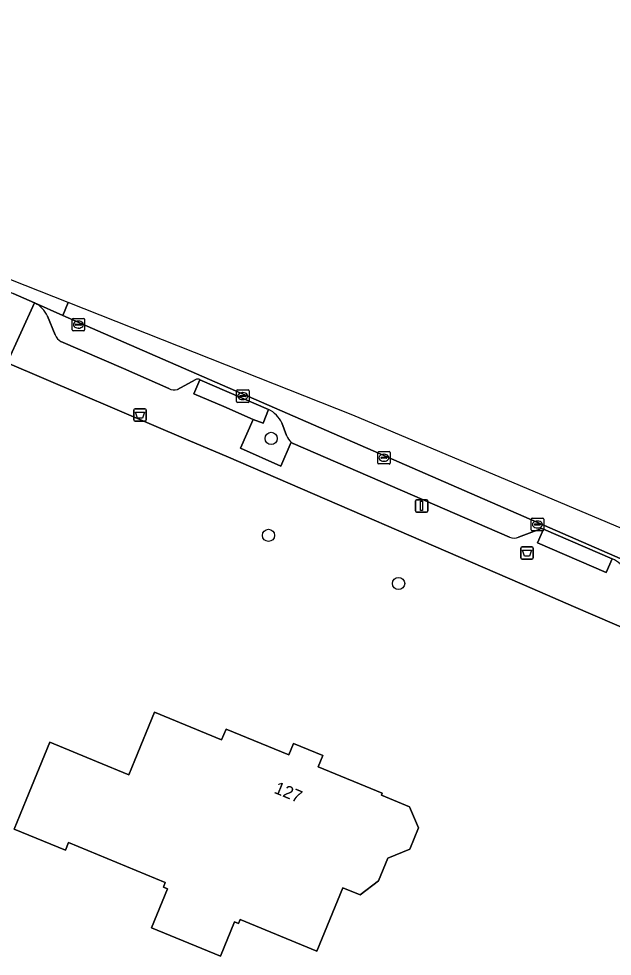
# Model space of a CAD drawing. Extents: x 159371 to 159986, y 382987 to 383597.
# Drawn here: x 159771.8 to 159819.4, y 383510.4 to 383585.6 of the extents above; entities that cross this region are included whole.
import ezdxf

# ---------------------------------------------------------------- set-up
doc = ezdxf.new("R2010")
doc.units = 0
for name, color, linetype in [('IMGEO_Afvalbak', 7, 'Continuous'), ('IMGEO_Boom', 7, 'Continuous'), ('IMGEO_Erf', 7, 'Continuous'), ('IMGEO_Groenvoorziening', 7, 'Continuous'), ('IMGEO_Kolk', 7, 'Continuous'), ('IMGEO_Lichtmast', 7, 'Continuous'), ('IMGEO_Pand', 7, 'Continuous'), ('IMGEO_Pand_nummerreeks', 7, 'Continuous'), ('IMGEO_Parkeervlak_open', 7, 'Continuous'), ('IMGEO_Rijbaan_lokaal_open', 7, 'Continuous'), ('IMGEO_Voetpad_open', 7, 'Continuous')]:
    doc.layers.add(name, color=color, linetype=linetype)

msp = doc.modelspace()

# ---------------------------------------------------------------- linework, layer by layer
at = {"layer": 'IMGEO_Afvalbak'}
for p, q in [((159780.996, 383553.438), (159780.996, 383554.238)), ((159780.996, 383554.238), (159780.996, 383553.438)), ((159781.096, 383554.338), (159781.886, 383554.338)), ((159781.886, 383554.338), (159781.096, 383554.338)), ((159781.986, 383554.238), (159781.986, 383553.438)), ((159781.986, 383553.438), (159781.986, 383554.238)), ((159781.886, 383553.338), (159781.096, 383553.338)), ((159781.096, 383553.338), (159781.886, 383553.338)), ((159812.046, 383542.362), (159812.046, 383543.162)), ((159812.046, 383543.162), (159812.046, 383542.362)), ((159812.146, 383543.262), (159812.936, 383543.262)), ((159812.936, 383543.262), (159812.146, 383543.262)), ((159813.036, 383543.162), (159813.036, 383542.362)), ((159813.036, 383542.362), (159813.036, 383543.162)), ((159812.936, 383542.262), (159812.146, 383542.262)), ((159812.146, 383542.262), (159812.936, 383542.262))]:
    msp.add_line(p, q, dxfattribs=at)
for points in [[(159781.139, 383554.052), (159781.843, 383554.052), (159781.694, 383553.582), (159781.288, 383553.582), (159781.139, 383554.052)], [(159812.189, 383542.976), (159812.893, 383542.976), (159812.744, 383542.506), (159812.338, 383542.506), (159812.189, 383542.976)]]:
    msp.add_lwpolyline(points, dxfattribs=at)
for centre, start, end in [((159781.096, 383554.238), 90, 180), ((159781.096, 383554.238), 90, 180), ((159781.886, 383554.238), 0, 90), ((159781.886, 383554.238), 360, 90), ((159781.096, 383553.438), 180, 270), ((159781.096, 383553.438), 180, 270), ((159781.886, 383553.438), 270, 0), ((159781.886, 383553.438), 270, 0), ((159812.146, 383543.162), 90, 180), ((159812.146, 383543.162), 90, 180), ((159812.936, 383543.162), 0, 90), ((159812.936, 383543.162), 360, 90), ((159812.146, 383542.362), 180, 270), ((159812.146, 383542.362), 180, 270), ((159812.936, 383542.362), 270, 0), ((159812.936, 383542.362), 270, 0)]:
    msp.add_arc(centre, 0.1, start, end, dxfattribs=at)
at = {"layer": 'IMGEO_Boom'}
for centre in [(159792.012, 383551.954), (159791.801, 383544.177), (159802.241, 383540.317)]:
    msp.add_circle(centre, 0.489, dxfattribs=at)
at = {"layer": 'IMGEO_Erf'}
msp.add_lwpolyline([(159832.543, 383531.462), (159816.278, 383538.482), (159812.967, 383539.912), (159788.6, 383550.438), (159785.366, 383551.823), (159770.834, 383558.006)], dxfattribs=at)
msp.add_lwpolyline([(159782.404, 383512.694), (159783.695, 383515.837), (159783.37, 383515.97), (159783.522, 383516.34), (159775.765, 383519.529), (159775.515, 383518.919), (159771.401, 383520.61), (159772.363, 383522.951), (159774.263, 383527.575), (159777.99, 383526.044), (159780.59, 383524.976), (159781.067, 383526.138), (159782.647, 383529.983), (159788.039, 383527.767), (159788.396, 383528.635), (159793.433, 383526.565), (159793.808, 383527.476), (159796.166, 383526.507), (159795.792, 383525.598), (159800.927, 383523.487), (159800.866, 383523.338), (159803.128, 383522.409), (159803.838, 383520.706), (159803.142, 383519.013), (159801.377, 383518.276), (159800.632, 383516.462), (159799.169, 383515.334), (159797.773, 383515.908), (159795.684, 383510.825), (159789.527, 383513.356), (159789.395, 383513.035), (159789.076, 383513.166), (159787.946, 383510.416)], close=True, dxfattribs=at)
at = {"layer": 'IMGEO_Groenvoorziening'}
for points in [[(159791.801, 383554.267), (159791.361, 383553.168), (159790.568, 383553.476), (159789.546, 383551.174), (159792.799, 383549.735), (159793.631, 383551.651)], [(159793.256, 383552.182), (159792.863, 383553.191)]]:
    msp.add_lwpolyline(points, dxfattribs=at)
for centre, radius, start, end in [((159790.96, 383552.375), 2.071, 23.21232, 66.03733), ((159794.527, 383552.682), 1.366, 201.46093, 228.99967)]:
    msp.add_arc(centre, radius, start, end, dxfattribs=at)
at = {"layer": 'IMGEO_Kolk'}
for p, q in [((159776.046, 383560.654), (159776.046, 383561.506)), ((159776.121, 383561.58), (159776.973, 383561.58)), ((159776.534, 383561.36), (159776.559, 383561.36)), ((159777.047, 383561.506), (159777.047, 383560.654)), ((159776.973, 383560.58), (159776.121, 383560.58)), ((159776.305, 383561.074), (159776.305, 383561.086)), ((159776.743, 383561.037), (159776.345, 383561.037)), ((159776.348, 383561.123), (159776.746, 383561.123)), ((159776.557, 383560.8), (159776.532, 383560.8)), ((159776.789, 383561.086), (159776.789, 383561.074)), ((159789.237, 383554.921), (159789.237, 383555.773)), ((159789.312, 383555.847), (159790.164, 383555.847)), ((159789.496, 383555.341), (159789.496, 383555.353)), ((159789.934, 383555.304), (159789.536, 383555.304)), ((159789.539, 383555.39), (159789.937, 383555.39)), ((159789.725, 383555.627), (159789.75, 383555.627)), ((159789.98, 383555.353), (159789.98, 383555.341)), ((159790.238, 383555.773), (159790.238, 383554.921)), ((159790.164, 383554.847), (159789.312, 383554.847)), ((159789.748, 383555.067), (159789.723, 383555.067)), ((159800.566, 383549.975), (159800.566, 383550.827)), ((159800.641, 383550.901), (159801.493, 383550.901)), ((159801.054, 383550.681), (159801.079, 383550.681)), ((159801.567, 383550.827), (159801.567, 383549.975)), ((159800.825, 383550.395), (159800.825, 383550.407)), ((159801.263, 383550.358), (159800.865, 383550.358)), ((159800.868, 383550.444), (159801.266, 383550.444)), ((159801.077, 383550.121), (159801.052, 383550.121)), ((159801.309, 383550.407), (159801.309, 383550.395)), ((159801.493, 383549.901), (159800.641, 383549.901)), ((159812.882, 383544.621), (159812.882, 383545.473)), ((159812.957, 383545.547), (159813.809, 383545.547)), ((159813.883, 383545.473), (159813.883, 383544.621)), ((159813.141, 383545.041), (159813.141, 383545.053)), ((159813.579, 383545.004), (159813.181, 383545.004)), ((159813.184, 383545.09), (159813.582, 383545.09)), ((159813.393, 383544.767), (159813.368, 383544.767)), ((159813.37, 383545.327), (159813.395, 383545.327)), ((159813.625, 383545.053), (159813.625, 383545.041)), ((159813.809, 383544.547), (159812.957, 383544.547))]:
    msp.add_line(p, q, dxfattribs=at)
for points in [[(159776.046, 383560.654), (159776.046, 383561.506)], [(159776.121, 383561.58), (159776.973, 383561.58)], [(159777.047, 383561.506), (159777.047, 383560.654)], [(159776.973, 383560.58), (159776.121, 383560.58)], [(159789.237, 383554.921), (159789.237, 383555.773)], [(159789.312, 383555.847), (159790.164, 383555.847)], [(159790.238, 383555.773), (159790.238, 383554.921)], [(159790.164, 383554.847), (159789.312, 383554.847)], [(159800.566, 383549.975), (159800.566, 383550.827)], [(159800.641, 383550.901), (159801.493, 383550.901)], [(159801.567, 383550.827), (159801.567, 383549.975)], [(159801.493, 383549.901), (159800.641, 383549.901)], [(159812.882, 383544.621), (159812.882, 383545.473)], [(159812.957, 383545.547), (159813.809, 383545.547)], [(159813.883, 383545.473), (159813.883, 383544.621)], [(159813.809, 383544.547), (159812.957, 383544.547)]]:
    msp.add_lwpolyline(points, dxfattribs=at)
for centre, radius, start, end in [((159776.123, 383561.504), 0.0765, 91.55205, 178.44795), ((159776.123, 383561.504), 0.0765, 91.55205, 178.44795), ((159776.971, 383561.504), 0.0765, 1.55205, 88.44795), ((159776.971, 383561.504), 0.0765, 1.55205, 88.44795), ((159776.123, 383560.656), 0.0765, 181.55205, 268.44795), ((159776.123, 383560.656), 0.0765, 181.55205, 268.44795), ((159776.345, 383561.083), 0.0403, 85.87752, 175.75265), ((159776.342, 383561.073), 0.0366, 178.93798, 274.71019), ((159776.746, 383561.08), 0.043, 264.86636, 352.45326), ((159776.75, 383561.085), 0.0386, 1.73085, 96.63898), ((159776.971, 383560.656), 0.0765, 271.55205, 358.44795), ((159776.971, 383560.656), 0.0765, 271.55205, 358.44795), ((159789.314, 383555.771), 0.0765, 91.55205, 178.44795), ((159789.314, 383555.771), 0.0765, 91.55205, 178.44795), ((159789.536, 383555.35), 0.0403, 85.87752, 175.75265), ((159789.533, 383555.34), 0.0366, 178.93798, 274.71019), ((159789.937, 383555.347), 0.043, 264.86636, 352.45326), ((159789.941, 383555.352), 0.0386, 1.73085, 96.63898), ((159790.162, 383555.771), 0.0765, 1.55205, 88.44795), ((159790.162, 383555.771), 0.0765, 1.55205, 88.44795), ((159789.314, 383554.923), 0.0765, 181.55205, 268.44795), ((159789.314, 383554.923), 0.0765, 181.55205, 268.44795), ((159790.162, 383554.923), 0.0765, 271.55205, 358.44795), ((159790.162, 383554.923), 0.0765, 271.55205, 358.44795), ((159800.643, 383550.825), 0.0765, 91.55205, 178.44795), ((159800.643, 383550.825), 0.0765, 91.55205, 178.44795), ((159801.491, 383550.825), 0.0765, 1.55205, 88.44795), ((159801.491, 383550.825), 0.0765, 1.55205, 88.44795), ((159800.643, 383549.977), 0.0765, 181.55205, 268.44795), ((159800.643, 383549.977), 0.0765, 181.55205, 268.44795), ((159800.865, 383550.404), 0.0403, 85.87752, 175.75265), ((159800.862, 383550.394), 0.0366, 178.93798, 274.71019), ((159801.266, 383550.401), 0.043, 264.86636, 352.45326), ((159801.27, 383550.406), 0.0386, 1.73085, 96.63898), ((159801.491, 383549.977), 0.0765, 271.55205, 358.44795), ((159801.491, 383549.977), 0.0765, 271.55205, 358.44795), ((159812.959, 383545.471), 0.0765, 91.55205, 178.44795), ((159812.959, 383545.471), 0.0765, 91.55205, 178.44795), ((159813.807, 383545.471), 0.0765, 1.55205, 88.44795), ((159813.807, 383545.471), 0.0765, 1.55205, 88.44795), ((159813.181, 383545.05), 0.0403, 85.87752, 175.75265), ((159813.178, 383545.04), 0.0366, 178.93798, 274.71019), ((159813.582, 383545.047), 0.043, 264.86636, 352.45326), ((159813.586, 383545.052), 0.0386, 1.73085, 96.63898), ((159812.959, 383544.623), 0.0765, 181.55205, 268.44795), ((159812.959, 383544.623), 0.0765, 181.55205, 268.44795), ((159813.807, 383544.623), 0.0765, 271.55205, 358.44795), ((159813.807, 383544.623), 0.0765, 271.55205, 358.44795)]:
    msp.add_arc(centre, radius, start, end, dxfattribs=at)
for centre, major_axis, ratio, start_param, end_param in [((159776.533, 383561.08), (-0.387, 0.002), 0.722429, 4.712389, 7.853982), ((159776.558, 383561.08), (-0.39, 0.002), 0.717154, 1.570796, 4.712389), ((159789.724, 383555.347), (-0.387, 0.002), 0.722429, 4.712389, 7.853982), ((159789.749, 383555.347), (-0.39, 0.002), 0.717154, 1.570796, 4.712389), ((159801.053, 383550.401), (-0.387, 0.002), 0.722429, 4.712389, 7.853982), ((159801.078, 383550.401), (-0.39, 0.002), 0.717154, 1.570796, 4.712389), ((159813.369, 383545.047), (-0.387, 0.002), 0.722429, 4.712389, 7.853982), ((159813.394, 383545.047), (-0.39, 0.002), 0.717154, 1.570796, 4.712389)]:
    msp.add_ellipse(centre, major_axis=major_axis, ratio=ratio, start_param=start_param, end_param=end_param, dxfattribs=at)
at = {"layer": 'IMGEO_Lichtmast'}
for p, q in [((159803.589, 383546.139), (159803.589, 383546.939)), ((159803.589, 383546.939), (159803.589, 383546.139)), ((159803.689, 383547.039), (159804.479, 383547.039)), ((159804.479, 383547.039), (159803.689, 383547.039)), ((159804.579, 383546.939), (159804.579, 383546.139)), ((159804.579, 383546.139), (159804.579, 383546.939)), ((159804.479, 383546.039), (159803.689, 383546.039)), ((159803.689, 383546.039), (159804.479, 383546.039))]:
    msp.add_line(p, q, dxfattribs=at)
msp.add_lwpolyline([(159804.009, 383546.914), (159804.159, 383546.914), (159804.159, 383546.164), (159804.009, 383546.164), (159804.009, 383546.914)], dxfattribs=at)
for centre, start, end in [((159803.689, 383546.939), 90, 180), ((159803.689, 383546.939), 90, 180), ((159804.479, 383546.939), 0, 90), ((159804.479, 383546.939), 360, 90), ((159803.689, 383546.139), 180, 270), ((159803.689, 383546.139), 180, 270), ((159804.479, 383546.139), 270, 0), ((159804.479, 383546.139), 270, 0)]:
    msp.add_arc(centre, 0.1, start, end, dxfattribs=at)
at = {"layer": 'IMGEO_Pand'}
msp.add_lwpolyline([(159803.838, 383520.706), (159803.128, 383522.409), (159800.866, 383523.338), (159800.927, 383523.487), (159795.792, 383525.598), (159796.166, 383526.507), (159793.808, 383527.476), (159793.433, 383526.565), (159788.396, 383528.635), (159788.039, 383527.767), (159782.647, 383529.983), (159781.067, 383526.138), (159780.59, 383524.976), (159777.99, 383526.044), (159774.263, 383527.575), (159772.363, 383522.951), (159771.401, 383520.61), (159775.515, 383518.919), (159775.765, 383519.529), (159783.522, 383516.34), (159783.37, 383515.97), (159783.695, 383515.837), (159782.404, 383512.694), (159787.946, 383510.416), (159789.076, 383513.166), (159789.395, 383513.035), (159789.527, 383513.356), (159795.684, 383510.825), (159797.773, 383515.908), (159799.169, 383515.334), (159800.632, 383516.462), (159801.377, 383518.276), (159803.142, 383519.013)], close=True, dxfattribs=at)
at = {"layer": 'IMGEO_Parkeervlak_open'}
for points in [[(159778.119, 383560.596), (159775.308, 383561.823), (159773.028, 383562.816)], [(159774.067, 383561.751), (159774.686, 383560.262)], [(159842.799, 383532.409), (159840.647, 383533.344), (159778.119, 383560.596)], [(159775.15, 383559.728), (159780.155, 383557.549), (159783.806, 383555.952)], [(159784.495, 383555.89), (159785.927, 383556.659)], [(159786.288, 383556.664), (159791.801, 383554.267)], [(159792.863, 383553.191), (159793.256, 383552.182)], [(159793.773, 383551.544), (159811.143, 383544.04)], [(159811.87, 383544.032), (159813.562, 383544.676)], [(159813.868, 383544.67), (159819.383, 383542.284)]]:
    msp.add_lwpolyline(points, dxfattribs=at)
for centre, radius, start, end in [((159772.212, 383560.981), 2.009, 22.55262, 66.0314), ((159775.587, 383560.576), 0.954, 199.21955, 242.75611), ((159786.112, 383556.352), 0.358, 60.5163, 121.07074), ((159784.231, 383556.814), 0.961, 243.76926, 285.94686), ((159790.96, 383552.375), 2.071, 23.21232, 66.03733), ((159794.527, 383552.682), 1.366, 201.46093, 228.99967), ((159794.444, 383552.582), 1.236, 228.87793, 237.12448), ((159813.708, 383544.298), 0.406, 66.70627, 111.04712), ((159811.516, 383544.887), 0.925, 246.23394, 292.50513), ((159818.671, 383540.456), 1.961, 22.81883, 68.71744)]:
    msp.add_arc(centre, radius, start, end, dxfattribs=at)
at = {"layer": 'IMGEO_Rijbaan_lokaal_open'}
msp.add_lwpolyline([(159721.291, 383581.85), (159721.368, 383581.821), (159721.444, 383581.793), (159726.316, 383580.048), (159733.407, 383577.507), (159739.114, 383575.457), (159764.299, 383566.393), (159768.037, 383564.957), (159771.312, 383563.569), (159773.028, 383562.816), (159775.308, 383561.823), (159775.74, 383562.852), (159733.161, 383579.684), (159727.097, 383585.616)], dxfattribs=at)
msp.add_lwpolyline([(159841.625, 383535.678), (159829.216, 383540.909), (159798.574, 383553.825), (159775.74, 383562.852), (159775.308, 383561.823), (159778.119, 383560.596), (159840.647, 383533.344), (159841.625, 383535.678)], close=True, dxfattribs=at)
at = {"layer": 'IMGEO_Voetpad_open'}
for points in [[(159770.834, 383558.006), (159773.028, 383562.816), (159771.312, 383563.569)], [(159773.028, 383562.816), (159770.834, 383558.006), (159785.366, 383551.823), (159788.6, 383550.438), (159812.967, 383539.912), (159816.278, 383538.482), (159832.543, 383531.462)], [(159774.686, 383560.262), (159774.067, 383561.751)], [(159783.806, 383555.952), (159780.155, 383557.549), (159775.15, 383559.728)], [(159785.927, 383556.659), (159784.495, 383555.89)], [(159793.631, 383551.651), (159792.799, 383549.735), (159789.546, 383551.174), (159790.568, 383553.476), (159788.23, 383554.523), (159785.823, 383555.539), (159786.288, 383556.664)], [(159811.143, 383544.04), (159793.773, 383551.544)], [(159813.562, 383544.676), (159811.87, 383544.032)], [(159819.383, 383542.284), (159818.892, 383541.191), (159813.397, 383543.573), (159813.868, 383544.67)]]:
    msp.add_lwpolyline(points, dxfattribs=at)
for points in [[(159786.288, 383556.664), (159785.823, 383555.539), (159788.23, 383554.523), (159790.568, 383553.476), (159791.361, 383553.168), (159791.801, 383554.267)], [(159813.868, 383544.67), (159813.397, 383543.573), (159818.892, 383541.191), (159819.383, 383542.284)]]:
    msp.add_lwpolyline(points, close=True, dxfattribs=at)
for centre, radius, start, end in [((159772.212, 383560.981), 2.009, 22.55262, 66.0314), ((159775.587, 383560.576), 0.954, 199.21955, 242.75611), ((159786.112, 383556.352), 0.358, 60.5163, 121.07074), ((159784.231, 383556.814), 0.961, 243.76926, 285.94686), ((159794.444, 383552.582), 1.236, 228.87793, 237.12448), ((159813.708, 383544.298), 0.406, 66.70627, 111.04712), ((159811.516, 383544.887), 0.925, 246.23394, 292.50513), ((159818.671, 383540.456), 1.961, 22.81883, 68.71744)]:
    msp.add_arc(centre, radius, start, end, dxfattribs=at)

# ---------------------------------------------------------------- texts
at = {"layer": 'IMGEO_Pand_nummerreeks'}
msp.add_text('127', height=1, rotation=337.71194, dxfattribs=at).set_placement((159792.178, 383523.534))

doc.saveas('drawing.dxf')
